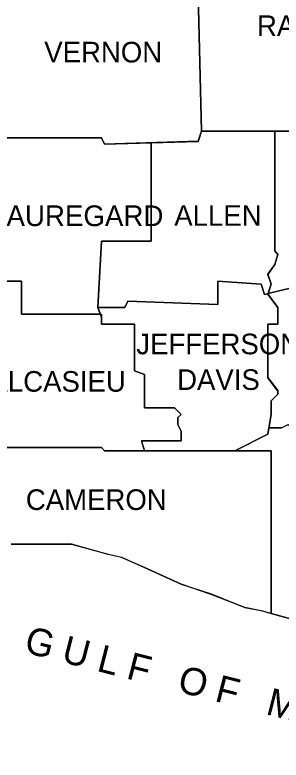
# Model space of a CAD drawing. Extents: x 0.19 to 2.82, y 0.04 to 1.79.
# Drawn here: x 2.26 to 2.3204, y 1.4248 to 1.594 of the extents above; entities that cross this region are included whole.
import ezdxf

# ---------------------------------------------------------------- set-up
doc = ezdxf.new("R2010")
doc.units = 0
for name, color, linetype in [('Dist03', 7, 'Continuous'), ('Dist07', 7, 'Continuous'), ('Dist08', 7, 'Continuous'), ('Standard Info', 7, 'Continuous')]:
    doc.layers.add(name, color=color, linetype=linetype)

msp = doc.modelspace()

# ---------------------------------------------------------------- linework, layer by layer
at = {"layer": 'Dist03'}
for points in [[(2.3469, 1.56308), (2.3454, 1.56308), (2.3454, 1.56758), (2.3439, 1.56917), (2.3424, 1.57067), (2.3424, 1.57292), (2.34015, 1.57292), (2.33782, 1.57292), (2.33557, 1.57367), (2.33482, 1.57592), (2.33407, 1.57592), (2.33257, 1.57517), (2.33182, 1.57367), (2.33024, 1.57217), (2.32799, 1.57067), (2.32649, 1.56758), (2.31899, 1.56758)], [(2.31899, 1.56758), (2.31899, 1.54042), (2.31965, 1.53958), (2.31899, 1.53733), (2.3174, 1.53508), (2.31815, 1.53283), (2.3174, 1.53058)], [(2.31732, 1.53075), (2.31965, 1.5275), (2.31965, 1.526), (2.31965, 1.52375), (2.3174, 1.52375), (2.3174, 1.51167), (2.31965, 1.50867), (2.31965, 1.50783), (2.31815, 1.50633), (2.31815, 1.50333), (2.3174, 1.49875), (2.3099, 1.495)], [(2.3099, 1.495), (2.31815, 1.495), (2.31815, 1.45833)], [(2.31815, 1.45808), (2.32424, 1.45642), (2.33257, 1.45725), (2.34015, 1.45492), (2.34165, 1.45492), (2.3469, 1.45642), (2.34765, 1.45642)]]:
    msp.add_lwpolyline(points, dxfattribs=at)
at = {"layer": 'Dist07'}
for points in [[(2.30232, 1.56758), (2.30157, 1.56533), (2.28032, 1.56458), (2.27965, 1.56608), (2.25765, 1.56608), (2.2539, 1.56383), (2.25007, 1.56683), (2.2494, 1.56533)], [(2.31899, 1.56758), (2.30232, 1.56758)], [(2.3174, 1.53058), (2.31815, 1.53283), (2.3174, 1.53508), (2.31899, 1.53733), (2.31965, 1.53958), (2.31899, 1.54042), (2.31899, 1.56758)], [(2.3099, 1.495), (2.3174, 1.49875), (2.31815, 1.50333), (2.31815, 1.50633), (2.31965, 1.50783), (2.31965, 1.50867), (2.3174, 1.51167), (2.3174, 1.52375), (2.31965, 1.52375), (2.31965, 1.526), (2.31965, 1.5275), (2.31732, 1.53075)], [(2.31815, 1.45833), (2.31815, 1.495), (2.3099, 1.495)], [(2.25915, 1.47383), (2.26824, 1.47383), (2.27282, 1.47383), (2.28115, 1.47158), (2.28415, 1.47083), (2.2894, 1.4685), (2.29774, 1.46475), (2.30457, 1.4625), (2.31215, 1.45942), (2.3159, 1.45875), (2.31815, 1.45808)]]:
    msp.add_lwpolyline(points, dxfattribs=at)
at = {"layer": 'Dist08'}
for points in [[(2.30232, 1.56758), (2.32649, 1.56758), (2.32799, 1.57067), (2.33024, 1.57217), (2.33182, 1.57367), (2.33257, 1.57517), (2.33407, 1.57592), (2.33482, 1.57592), (2.33557, 1.57367), (2.33782, 1.57292), (2.34015, 1.57292), (2.3424, 1.57292)], [(2.2494, 1.56533), (2.25007, 1.56683), (2.2539, 1.56383), (2.25765, 1.56608), (2.27965, 1.56608), (2.28032, 1.56458), (2.30157, 1.56533), (2.30232, 1.56758)]]:
    msp.add_lwpolyline(points, dxfattribs=at)
at = {"layer": 'Standard Info'}
msp.add_line((2.31765, 1.50025), (2.31774, 1.50025), dxfattribs=at)
for points in [[(2.29249, 1.60517), (2.29249, 1.60392), (2.29849, 1.60392), (2.29849, 1.59858), (2.30157, 1.59858), (2.30232, 1.56758)], [(2.29249, 1.60517), (2.29249, 1.60392), (2.29849, 1.60392), (2.29849, 1.59858), (2.30157, 1.59858), (2.30232, 1.56758)], [(2.30232, 1.56758), (2.30157, 1.59858), (2.29849, 1.59858), (2.29849, 1.60392), (2.29249, 1.60392), (2.29249, 1.60517)], [(2.29249, 1.60508), (2.29249, 1.60392), (2.29849, 1.60392), (2.29849, 1.59858), (2.30157, 1.59858), (2.30232, 1.56758)], [(2.3424, 1.57283), (2.34015, 1.57283), (2.33782, 1.57283), (2.33557, 1.57367), (2.33482, 1.57592), (2.33407, 1.57592), (2.33257, 1.57517), (2.33182, 1.57367), (2.33024, 1.57208), (2.32799, 1.57058), (2.32649, 1.56758), (2.30232, 1.56758)], [(2.31899, 1.56758), (2.32649, 1.56758), (2.32799, 1.57058), (2.33024, 1.57208), (2.33182, 1.57367), (2.33257, 1.57517), (2.33407, 1.57592), (2.33482, 1.57592), (2.33557, 1.57367), (2.33782, 1.57283), (2.34015, 1.57283), (2.3424, 1.57283), (2.3424, 1.57058), (2.3439, 1.56908), (2.3454, 1.56758), (2.3454, 1.56308), (2.3469, 1.56308)], [(2.30232, 1.56758), (2.30157, 1.56525), (2.28032, 1.56458), (2.27965, 1.56608), (2.25765, 1.56608), (2.2539, 1.56375), (2.25007, 1.56683), (2.2494, 1.56525)], [(2.2494, 1.56525), (2.25007, 1.56683), (2.2539, 1.56375), (2.25765, 1.56608), (2.27965, 1.56608), (2.28032, 1.56458), (2.2909, 1.56492)], [(2.2909, 1.56492), (2.30157, 1.56525), (2.30232, 1.56758)], [(2.30232, 1.56758), (2.31899, 1.56758)], [(2.3174, 1.5305), (2.31815, 1.53283), (2.3174, 1.535), (2.31899, 1.53733), (2.31965, 1.53958), (2.31899, 1.54033), (2.31899, 1.56758)], [(2.31899, 1.56758), (2.31899, 1.54033), (2.31965, 1.53958), (2.31899, 1.53733), (2.3174, 1.535), (2.31815, 1.53283), (2.31749, 1.53075)], [(2.27882, 1.5275), (2.27965, 1.54258), (2.2909, 1.54258), (2.2909, 1.56492)], [(2.2909, 1.56492), (2.2909, 1.54258), (2.27965, 1.54258), (2.27882, 1.5275), (2.2794, 1.526)], [(2.2794, 1.526), (2.26149, 1.526), (2.26149, 1.5335), (2.2539, 1.5335), (2.2539, 1.526), (2.23649, 1.526)], [(2.23649, 1.526), (2.2539, 1.526), (2.2539, 1.5335), (2.26149, 1.5335), (2.26149, 1.526), (2.2794, 1.526)], [(2.3174, 1.53067), (2.31665, 1.5305), (2.3159, 1.53283), (2.30607, 1.5335), (2.30607, 1.52825), (2.28565, 1.529), (2.2849, 1.5275), (2.27882, 1.5275)], [(2.27882, 1.5275), (2.2849, 1.5275), (2.28565, 1.529), (2.30607, 1.52825), (2.30607, 1.5335), (2.3159, 1.53283), (2.31665, 1.5305), (2.3174, 1.53067)], [(2.32724, 1.532), (2.32274, 1.532), (2.31749, 1.53075)], [(2.31749, 1.53075), (2.32274, 1.532), (2.32799, 1.532), (2.34465, 1.532), (2.34465, 1.52825), (2.34924, 1.52825), (2.34924, 1.52142), (2.35299, 1.51842), (2.35224, 1.51692)], [(2.31732, 1.53067), (2.31965, 1.5275), (2.31965, 1.526), (2.31965, 1.52375), (2.3174, 1.52375), (2.3174, 1.51158), (2.31965, 1.50858), (2.31965, 1.50783), (2.31815, 1.50633), (2.31815, 1.50325), (2.3174, 1.49875), (2.3099, 1.495)], [(2.31774, 1.50025), (2.31815, 1.50325), (2.31815, 1.50633), (2.31965, 1.50783), (2.31965, 1.50858), (2.3174, 1.51158), (2.3174, 1.52375), (2.31965, 1.52375), (2.31965, 1.526), (2.31965, 1.5275), (2.31732, 1.53067)], [(2.27965, 1.52375), (2.27965, 1.52525), (2.27882, 1.5275)], [(2.27965, 1.526), (2.27965, 1.52375)], [(2.2894, 1.495), (2.28874, 1.49725), (2.29774, 1.49725), (2.29774, 1.4995), (2.29699, 1.501), (2.29699, 1.50258), (2.29774, 1.50325), (2.29624, 1.50475), (2.2894, 1.50475), (2.2894, 1.51233), (2.28715, 1.51317), (2.28715, 1.52375), (2.27965, 1.52375)], [(2.27965, 1.52375), (2.28715, 1.52375), (2.28715, 1.51317), (2.2894, 1.51233), (2.2894, 1.50475), (2.29624, 1.50475), (2.29774, 1.50325), (2.29699, 1.50258), (2.29699, 1.501), (2.29774, 1.4995), (2.29774, 1.49725), (2.28874, 1.49725), (2.2894, 1.495)], [(2.31765, 1.50025), (2.32049, 1.50025), (2.32199, 1.501), (2.32424, 1.4995), (2.32499, 1.4995), (2.32574, 1.49875), (2.32799, 1.49725), (2.32957, 1.4965), (2.33182, 1.4965), (2.33332, 1.4965), (2.33557, 1.498), (2.33632, 1.49875), (2.33707, 1.4995), (2.33857, 1.50175), (2.34015, 1.50325), (2.34165, 1.50408)], [(2.31815, 1.45867), (2.31815, 1.495), (2.3099, 1.495), (2.3174, 1.49875), (2.31765, 1.50025)], [(2.32049, 1.50025), (2.31765, 1.50025)], [(2.2894, 1.495), (2.28032, 1.495), (2.27965, 1.49575), (2.2494, 1.49575), (2.24557, 1.4965), (2.23424, 1.4965)], [(2.23424, 1.4965), (2.24557, 1.4965), (2.2494, 1.49575), (2.27965, 1.49575), (2.28032, 1.495), (2.3099, 1.495)], [(2.3099, 1.495), (2.2894, 1.495)], [(2.3099, 1.495), (2.31815, 1.495), (2.31815, 1.45825)], [(2.31815, 1.45808), (2.3159, 1.45867), (2.31215, 1.45942), (2.30457, 1.46242), (2.29774, 1.46475), (2.2894, 1.4685), (2.28415, 1.47075), (2.28115, 1.4715), (2.27282, 1.47383), (2.26824, 1.47383), (2.25915, 1.47383)], [(2.34765, 1.45642), (2.3469, 1.45642), (2.34165, 1.45492), (2.34015, 1.45492), (2.33257, 1.45717), (2.32424, 1.45642), (2.31815, 1.45808)]]:
    msp.add_lwpolyline(points, dxfattribs=at)

# ---------------------------------------------------------------- texts
for s, height, p in [('RAPIDES', 0.004679, (2.31494, 1.58917)), ('VERNON', 0.004679, (2.26664, 1.58317)), ('BEAUREGARD', 0.0047, (2.24968, 1.54601)), ('ALLEN', 0.004679, (2.29616, 1.54608)), ('JEFFERSON', 0.004679, (2.28754, 1.51692)), ('CALCASIEU', 0.004679, (2.24969, 1.50842)), ('DAVIS', 0.004679, (2.2968, 1.50883)), ('CAMERON', 0.004679, (2.26246, 1.48158))]:
    msp.add_text(s, height=height, dxfattribs=at).set_placement(p)
msp.add_text('G U L F   O F   M E X I C O', height=0.0062, rotation=345.6507, dxfattribs=at).set_placement((2.26182, 1.4493))

doc.saveas('drawing.dxf')
